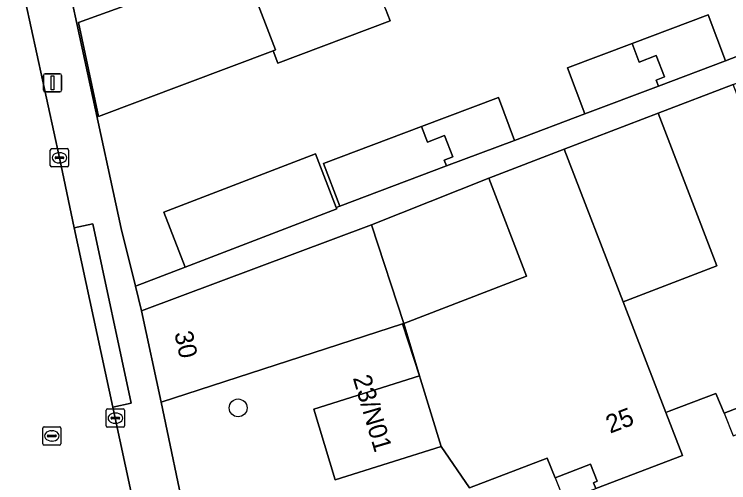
# Model space of a CAD drawing. Extents: x 159262 to 160143, y 383399 to 384319.
# Drawn here: x 159407.05 to 159446.11, y 383686.69 to 383712.34 of the extents above; entities that cross this region are included whole.
import ezdxf

# ---------------------------------------------------------------- set-up
doc = ezdxf.new("R2010")
doc.units = 0
for name, color, linetype in [('IMGEO_Boom', 7, 'Continuous'), ('IMGEO_Erf', 7, 'Continuous'), ('IMGEO_Kolk', 7, 'Continuous'), ('IMGEO_Lichtmast', 7, 'Continuous'), ('IMGEO_Muur', 7, 'Continuous'), ('IMGEO_Pand', 7, 'Continuous'), ('IMGEO_Pand_nummerreeks', 7, 'Continuous'), ('IMGEO_Pand_overbouw', 7, 'Continuous'), ('IMGEO_Rijbaan_lokaal_open', 7, 'Continuous'), ('IMGEO_Rioolput', 7, 'Continuous'), ('IMGEO_Voetpad_open', 7, 'Continuous')]:
    doc.layers.add(name, color=color, linetype=linetype)

msp = doc.modelspace()

# ---------------------------------------------------------------- linework, layer by layer
at = {"layer": 'IMGEO_Boom'}
msp.add_circle((159419.283, 383690.786), 0.489, dxfattribs=at)
at = {"layer": 'IMGEO_Erf'}
for points in [[(159409.505, 383716.326), (159412.893, 383700.61), (159413.681, 383697.451), (159416.385, 383698.491), (159415.225, 383701.507), (159423.514, 383704.695), (159424.645, 383701.755), (159424.841, 383701.83), (159423.961, 383704.167), (159429.312, 383706.183), (159433.524, 383707.771), (159434.404, 383705.433), (159438.242, 383706.88), (159437.291, 383709.406), (159440.824, 383710.737), (159444.985, 383712.306), (159445.937, 383709.78), (159449.626, 383711.226), (159448.675, 383713.719)], [(159410.549, 383711.888), (159413.684, 383713.02)], [(159427.347, 383712.627), (159427.598, 383711.98), (159421.459, 383709.663), (159421.205, 383710.337), (159411.653, 383706.731), (159410.549, 383711.888)], [(159438.712, 383686.682), (159438.913, 383686.767), (159438.557, 383687.709), (159436.62, 383686.956), (159436.185, 383688.037), (159431.935, 383686.411), (159430.379, 383688.675), (159424.584, 383686.839), (159423.418, 383690.708), (159429.205, 383692.541), (159428.265, 383695.382), (159415.08, 383691.104), (159416.485, 383684.382)], [(159447.792, 383691.248), (159445.855, 383690.495), (159445.415, 383691.579), (159442.857, 383690.602), (159442.676, 383690.533), (159443.581, 383688.189), (159438.836, 383686.372)]]:
    msp.add_lwpolyline(points, dxfattribs=at)
for points in [[(159442.249, 383706.913), (159437.112, 383704.944), (159440.336, 383696.595), (159440.493, 383696.655), (159445.452, 383698.556)], [(159432.997, 383703.367), (159426.583, 383700.81), (159428.339, 383695.406), (159435.054, 383698)]]:
    msp.add_lwpolyline(points, close=True, dxfattribs=at)
at = {"layer": 'IMGEO_Kolk'}
for p, q in [((159409.013, 383704.053), (159409.013, 383704.905)), ((159409.088, 383704.979), (159409.94, 383704.979)), ((159409.501, 383704.759), (159409.526, 383704.759)), ((159410.014, 383704.905), (159410.014, 383704.053)), ((159409.272, 383704.473), (159409.272, 383704.485)), ((159409.71, 383704.436), (159409.312, 383704.436)), ((159409.315, 383704.522), (159409.713, 383704.522)), ((159409.756, 383704.485), (159409.756, 383704.473)), ((159409.94, 383703.979), (159409.088, 383703.979)), ((159409.524, 383704.199), (159409.499, 383704.199)), ((159412.072, 383689.801), (159412.072, 383690.653)), ((159412.147, 383690.727), (159412.999, 383690.727)), ((159413.073, 383690.653), (159413.073, 383689.801)), ((159412.374, 383690.27), (159412.772, 383690.27)), ((159412.56, 383690.507), (159412.585, 383690.507)), ((159412.331, 383690.221), (159412.331, 383690.233)), ((159412.769, 383690.184), (159412.371, 383690.184)), ((159412.583, 383689.947), (159412.558, 383689.947)), ((159412.815, 383690.233), (159412.815, 383690.221)), ((159412.999, 383689.727), (159412.147, 383689.727))]:
    msp.add_line(p, q, dxfattribs=at)
for points in [[(159409.013, 383704.053), (159409.013, 383704.905)], [(159409.088, 383704.979), (159409.94, 383704.979)], [(159410.014, 383704.905), (159410.014, 383704.053)], [(159409.94, 383703.979), (159409.088, 383703.979)], [(159412.072, 383689.801), (159412.072, 383690.653)], [(159412.147, 383690.727), (159412.999, 383690.727)], [(159413.073, 383690.653), (159413.073, 383689.801)], [(159412.999, 383689.727), (159412.147, 383689.727)]]:
    msp.add_lwpolyline(points, dxfattribs=at)
for centre, radius, start, end in [((159409.09, 383704.903), 0.0765, 91.552, 178.448), ((159409.09, 383704.903), 0.0765, 91.552, 178.448), ((159409.938, 383704.903), 0.0765, 1.552, 88.448), ((159409.938, 383704.903), 0.0765, 1.552, 88.448), ((159409.312, 383704.482), 0.0403, 85.8775, 175.7526), ((159409.309, 383704.472), 0.0366, 178.938, 274.7102), ((159409.713, 383704.479), 0.043, 264.8664, 352.4533), ((159409.717, 383704.484), 0.0386, 1.7309, 96.639), ((159409.09, 383704.055), 0.0765, 181.552, 268.448), ((159409.09, 383704.055), 0.0765, 181.552, 268.448), ((159409.938, 383704.055), 0.0765, 271.552, 358.448), ((159409.938, 383704.055), 0.0765, 271.552, 358.448), ((159412.149, 383690.651), 0.0765, 91.552, 178.448), ((159412.149, 383690.651), 0.0765, 91.552, 178.448), ((159412.997, 383690.651), 0.0765, 1.552, 88.448), ((159412.997, 383690.651), 0.0765, 1.552, 88.448), ((159412.371, 383690.23), 0.0403, 85.8775, 175.7526), ((159412.776, 383690.232), 0.0386, 1.7309, 96.639), ((159412.368, 383690.22), 0.0366, 178.938, 274.7102), ((159412.772, 383690.227), 0.043, 264.8664, 352.4533), ((159412.149, 383689.803), 0.0765, 181.552, 268.448), ((159412.149, 383689.803), 0.0765, 181.552, 268.448), ((159412.997, 383689.803), 0.0765, 271.552, 358.448), ((159412.997, 383689.803), 0.0765, 271.552, 358.448)]:
    msp.add_arc(centre, radius, start, end, dxfattribs=at)
for centre, major_axis, ratio, start_param, end_param in [((159409.5, 383704.479), (-0.387, 0.002), 0.722429, 4.712389, 7.853982), ((159409.525, 383704.479), (-0.39, 0.002), 0.717154, 1.570796, 4.712389), ((159412.559, 383690.227), (-0.387, 0.002), 0.722429, 4.712389, 7.853982), ((159412.584, 383690.227), (-0.39, 0.002), 0.717154, 1.570796, 4.712389)]:
    msp.add_ellipse(centre, major_axis=major_axis, ratio=ratio, start_param=start_param, end_param=end_param, dxfattribs=at)
at = {"layer": 'IMGEO_Lichtmast'}
for p, q in [((159408.739, 383709.083), (159409.529, 383709.083)), ((159409.529, 383709.083), (159408.739, 383709.083)), ((159408.639, 383708.183), (159408.639, 383708.983)), ((159408.639, 383708.983), (159408.639, 383708.183)), ((159409.629, 383708.983), (159409.629, 383708.183)), ((159409.629, 383708.183), (159409.629, 383708.983)), ((159409.529, 383708.083), (159408.739, 383708.083)), ((159408.739, 383708.083), (159409.529, 383708.083))]:
    msp.add_line(p, q, dxfattribs=at)
msp.add_lwpolyline([(159409.059, 383708.958), (159409.209, 383708.958), (159409.209, 383708.208), (159409.059, 383708.208), (159409.059, 383708.958)], dxfattribs=at)
for centre, start, end in [((159408.739, 383708.983), 90, 180), ((159408.739, 383708.983), 90, 180), ((159409.529, 383708.983), 0, 90), ((159409.529, 383708.983), 360, 90), ((159408.739, 383708.183), 180, 270), ((159408.739, 383708.183), 180, 270), ((159409.529, 383708.183), 270, 0), ((159409.529, 383708.183), 270, 0)]:
    msp.add_arc(centre, 0.1, start, end, dxfattribs=at)
at = {"layer": 'IMGEO_Muur'}
msp.add_lwpolyline([(159428.339, 383695.406), (159429.205, 383692.541)], dxfattribs=at)
at = {"layer": 'IMGEO_Pand'}
for points in [[(159423.355, 383722.908), (159423.17, 383722.837), (159423.341, 383722.391), (159417.565, 383720.17), (159421.331, 383710.384), (159421.205, 383710.337), (159421.459, 383709.663), (159427.598, 383711.98), (159427.347, 383712.627)], [(159417.565, 383720.17), (159412.192, 383718.103), (159412.039, 383718.501), (159411.635, 383718.346), (159413.684, 383713.02), (159410.549, 383711.888), (159411.653, 383706.731), (159421.205, 383710.337), (159421.331, 383710.384)], [(159440.824, 383710.737), (159441.217, 383709.722), (159442.149, 383710.084), (159442.601, 383708.918), (159442.136, 383708.737), (159442.267, 383708.397), (159445.937, 383709.78), (159444.985, 383712.306)], [(159442.149, 383710.084), (159441.217, 383709.722), (159440.824, 383710.737), (159437.291, 383709.406), (159438.242, 383706.88), (159442.267, 383708.397), (159442.136, 383708.737), (159442.601, 383708.918)], [(159449.577, 383700.137), (159446.353, 383708.486), (159442.249, 383706.913), (159445.452, 383698.556), (159440.493, 383696.655), (159440.336, 383696.595), (159442.676, 383690.533), (159442.857, 383690.602), (159445.415, 383691.579), (159445.855, 383690.495), (159447.792, 383691.248), (159448.148, 383690.306), (159447.947, 383690.221), (159448.071, 383689.911), (159452.823, 383691.731), (159451.92, 383694.07)], [(159433.524, 383707.771), (159429.312, 383706.183), (159429.638, 383705.342), (159430.57, 383705.704), (159431.022, 383704.538), (159430.557, 383704.357), (159430.683, 383704.031), (159434.404, 383705.433)], [(159430.683, 383704.031), (159430.557, 383704.357), (159431.022, 383704.538), (159430.57, 383705.704), (159429.638, 383705.342), (159429.312, 383706.183), (159423.961, 383704.167), (159424.841, 383701.83)], [(159424.674, 383701.679), (159424.645, 383701.755), (159423.514, 383704.695), (159415.225, 383701.507), (159416.385, 383698.491)], [(159440.336, 383696.595), (159437.112, 383704.944), (159432.997, 383703.367), (159435.054, 383698), (159428.339, 383695.406), (159428.265, 383695.382), (159429.205, 383692.541), (159429.262, 383692.352), (159430.379, 383688.675), (159431.935, 383686.411), (159436.185, 383688.037), (159436.62, 383686.956), (159438.557, 383687.709), (159438.913, 383686.767), (159438.712, 383686.682), (159438.836, 383686.372), (159443.581, 383688.189), (159442.676, 383690.533)], [(159426.583, 383700.81), (159413.994, 383696.095), (159415.08, 383691.104), (159428.265, 383695.382), (159428.339, 383695.406)], [(159430.379, 383688.675), (159429.262, 383692.352), (159429.205, 383692.541), (159423.418, 383690.708), (159424.584, 383686.839)]]:
    msp.add_lwpolyline(points, close=True, dxfattribs=at)
at = {"layer": 'IMGEO_Pand_overbouw'}
for points in [[(159447.947, 383690.221), (159448.148, 383690.306), (159447.792, 383691.248), (159445.855, 383690.495), (159446.358, 383689.255), (159448.071, 383689.911)], [(159438.712, 383686.682), (159438.913, 383686.767), (159438.557, 383687.709), (159436.62, 383686.956), (159437.12, 383685.715), (159438.836, 383686.372)]]:
    msp.add_lwpolyline(points, close=True, dxfattribs=at)
at = {"layer": 'IMGEO_Rijbaan_lokaal_open'}
msp.add_lwpolyline([(159421.322, 383649.53), (159416.353, 383672.587), (159412.568, 383690.227), (159412.425, 383690.83), (159410.318, 383700.636), (159409.509, 383704.479), (159407.045, 383715.879)], dxfattribs=at)
at = {"layer": 'IMGEO_Rioolput'}
for p, q in [((159408.597, 383688.826), (159408.597, 383689.678)), ((159408.672, 383689.752), (159409.524, 383689.752)), ((159409.085, 383689.532), (159409.11, 383689.532)), ((159409.598, 383689.678), (159409.598, 383688.826)), ((159408.856, 383689.246), (159408.856, 383689.258)), ((159409.294, 383689.209), (159408.896, 383689.209)), ((159408.899, 383689.295), (159409.297, 383689.295)), ((159409.34, 383689.258), (159409.34, 383689.246)), ((159409.524, 383688.752), (159408.672, 383688.752)), ((159409.108, 383688.972), (159409.083, 383688.972))]:
    msp.add_line(p, q, dxfattribs=at)
for points in [[(159408.597, 383688.826), (159408.597, 383689.678)], [(159408.672, 383689.752), (159409.524, 383689.752)], [(159409.598, 383689.678), (159409.598, 383688.826)], [(159409.524, 383688.752), (159408.672, 383688.752)]]:
    msp.add_lwpolyline(points, dxfattribs=at)
for centre, radius, start, end in [((159408.674, 383689.676), 0.0765, 91.552, 178.448), ((159408.674, 383689.676), 0.0765, 91.552, 178.448), ((159409.522, 383689.676), 0.0765, 1.552, 88.448), ((159409.522, 383689.676), 0.0765, 1.552, 88.448), ((159408.896, 383689.255), 0.0403, 85.8775, 175.7526), ((159408.893, 383689.245), 0.0366, 178.938, 274.7102), ((159409.297, 383689.252), 0.043, 264.8664, 352.4533), ((159409.301, 383689.257), 0.0386, 1.7309, 96.639), ((159408.674, 383688.828), 0.0765, 181.552, 268.448), ((159408.674, 383688.828), 0.0765, 181.552, 268.448), ((159409.522, 383688.828), 0.0765, 271.552, 358.448), ((159409.522, 383688.828), 0.0765, 271.552, 358.448)]:
    msp.add_arc(centre, radius, start, end, dxfattribs=at)
for centre, major_axis, ratio, start_param, end_param in [((159409.084, 383689.252), (-0.387, 0.002), 0.722429, 4.712389, 7.853982), ((159409.109, 383689.252), (-0.39, 0.002), 0.717154, 1.570796, 4.712389)]:
    msp.add_ellipse(centre, major_axis=major_axis, ratio=ratio, start_param=start_param, end_param=end_param, dxfattribs=at)
at = {"layer": 'IMGEO_Voetpad_open'}
for points in [[(159419.007, 383672.947), (159417.143, 383681.455), (159416.485, 383684.382), (159415.08, 383691.104), (159413.994, 383696.095), (159413.681, 383697.451), (159412.893, 383700.61), (159409.505, 383716.326)], [(159407.045, 383715.879), (159409.509, 383704.479), (159410.318, 383700.636), (159411.335, 383700.854), (159413.442, 383691.048), (159412.425, 383690.83), (159412.568, 383690.227), (159416.353, 383672.587), (159421.322, 383649.53)], [(159453.776, 383712.81), (159449.626, 383711.226), (159445.937, 383709.78), (159442.267, 383708.397), (159438.242, 383706.88), (159434.404, 383705.433), (159430.683, 383704.031), (159424.841, 383701.83), (159424.645, 383701.755), (159424.674, 383701.679), (159416.385, 383698.491), (159413.681, 383697.451), (159413.994, 383696.095), (159426.583, 383700.81), (159432.997, 383703.367), (159437.112, 383704.944), (159442.249, 383706.913), (159446.353, 383708.486), (159451.502, 383710.46), (159455.588, 383712.026), (159460.746, 383714.002)]]:
    msp.add_lwpolyline(points, dxfattribs=at)
msp.add_lwpolyline([(159412.425, 383690.83), (159413.442, 383691.048), (159411.335, 383700.854), (159410.318, 383700.636)], close=True, dxfattribs=at)

# ---------------------------------------------------------------- texts
at = {"layer": 'IMGEO_Pand_nummerreeks'}
for s, rotation, p in [('30', 282.2783, (159415.792, 383694.884)), ('23/N01', 286.3895, (159425.55, 383692.434)), ('25', 20.9531, (159439.626, 383689.373))]:
    msp.add_text(s, height=1, rotation=rotation, dxfattribs=at).set_placement(p)

doc.saveas('drawing.dxf')
